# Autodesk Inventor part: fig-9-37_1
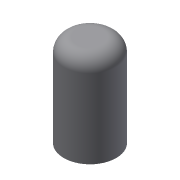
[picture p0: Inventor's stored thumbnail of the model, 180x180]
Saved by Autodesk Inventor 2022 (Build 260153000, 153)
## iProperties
Created: 2013-03
Part Number: fig-9-37_1
Material: Generic
Document SubType Name: Modeling
Designer: CADCIM
Density: 1 g/cm^3
Appearance: Default
Author: CADCIM
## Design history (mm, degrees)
sketch "Sketch1"
  geometry: C1 r 10 at (0, 0); 1 further point
  constraints: 1 centre point, 1 coincident
  dimensions: "d0" = 20 diameter of C1
extrude "Extrusion1" new body sketch "Sketch1" distance "d2" = 35; taper "d3" = 0 deg
fillet "Fillet1" dims "d4" = 5
shell "Shell1" dims "d5" = 2
body "Solid1"
